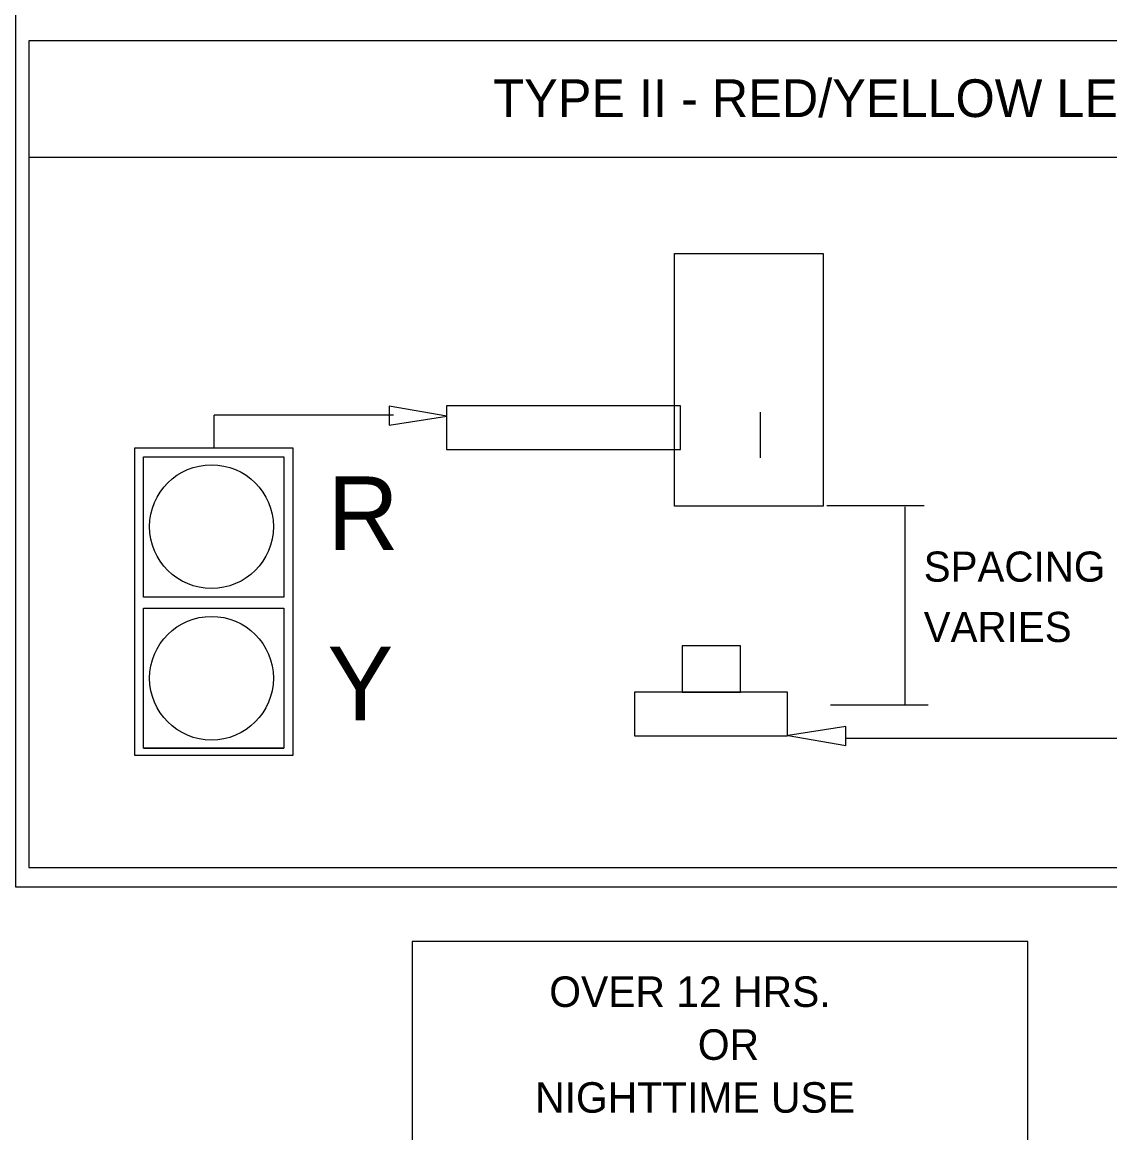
# Model space of a CAD drawing. Extents: x 21.7 to 29.1, y 5.9 to 16.2.
# Drawn here: x 25.794 to 27.525, y 11.205 to 12.972 of the extents above; entities that cross this region are included whole.
import ezdxf

# ---------------------------------------------------------------- set-up
doc = ezdxf.new("R2010")
doc.units = 0
for name, color, linetype in [('DETL-DIMS', 7, 'Continuous'), ('DETL-LINE', 7, 'Continuous'), ('DETL-NOTE', 7, 'Continuous')]:
    doc.layers.add(name, color=color, linetype=linetype)

msp = doc.modelspace()

# ---------------------------------------------------------------- linework, layer by layer
at = {"layer": 'DETL-DIMS'}
for p, q in [((27.0741, 12.2032), (27.2295, 12.2032)), ((27.1983, 12.2011), (27.1983, 11.886)), ((27.08, 11.886), (27.2354, 11.886))]:
    msp.add_line(p, q, dxfattribs=at)
for points in [[(26.3775, 12.3612), (26.3775, 12.3308), (26.4695, 12.3456)], [(27.1046, 11.8212), (27.1046, 11.8516), (27.0126, 11.8368)]]:
    msp.add_lwpolyline(points, close=True, dxfattribs=at)
at = {"layer": 'DETL-LINE'}
for p, q in [((26.3847, 12.3468), (26.0992, 12.3468)), ((26.0992, 12.2944), (26.0992, 12.3468)), ((26.9681, 12.3516), (26.9681, 12.2788)), ((25.9865, 12.0572), (25.9865, 12.2805)), ((25.9865, 12.2805), (26.2098, 12.2805)), ((26.2098, 12.2805), (26.2098, 12.0572)), ((26.2098, 12.0572), (25.9865, 12.0572)), ((25.9865, 11.8167), (25.9865, 12.0399)), ((25.9865, 12.0399), (26.2098, 12.0399)), ((26.2098, 12.0399), (26.2098, 11.8167)), ((27.1046, 11.833), (27.7835, 11.833)), ((25.9865, 11.8167), (26.2098, 11.8167)), ((26.2098, 11.8167), (25.9865, 11.8167)), ((27.3944, 11.5089), (26.4145, 11.5089)), ((26.4145, 11.5089), (26.4145, 7.6665)), ((27.3944, 7.6665), (27.3944, 11.5089))]:
    msp.add_line(p, q, dxfattribs=at)
for points in [[(25.7831, 11.5962), (29.0092, 11.5962), (29.0092, 14.3652), (25.7831, 14.3652)], [(25.8041, 11.6269), (28.9793, 11.6269), (28.9793, 12.9429), (25.8041, 12.9429)], [(28.9732, 12.7569), (25.8041, 12.7569), (25.8041, 11.6269), (28.9732, 11.6269)], [(26.8319, 12.2021), (26.8319, 12.6043), (27.0684, 12.6043), (27.0684, 12.2021)], [(26.8414, 12.3619), (26.469, 12.3619), (26.469, 12.2922), (26.8414, 12.2922)], [(25.9729, 12.295), (26.2243, 12.295), (26.2243, 11.805), (25.9729, 11.805)], [(26.844, 11.906), (26.937, 11.906), (26.937, 11.9796), (26.844, 11.9796)], [(26.7684, 11.906), (26.7684, 11.8365), (27.0119, 11.8365), (27.0119, 11.906)]]:
    msp.add_lwpolyline(points, close=True, dxfattribs=at)
for centre in [(26.0949, 12.1695), (26.0949, 11.9282)]:
    msp.add_circle(centre, 0.0985, dxfattribs=at)

# ---------------------------------------------------------------- texts
for s, p in [('OVER 12 HRS.', (26.6325, 11.405)), ('OR', (26.869, 11.3208)), ('NIGHTTIME USE', (26.61, 11.2366))]:
    msp.add_text(s, height=0.0486, dxfattribs=at).set_placement(p)
at = {"layer": 'DETL-NOTE'}
for s, height, p in [('TYPE II - RED/YELLOW LENS AFAD', 0.06, (26.5435, 12.8215)), ('R', 0.1172, (26.2796, 12.1322)), ('SPACING', 0.048, (27.2285, 12.0819)), ('VARIES', 0.048, (27.2285, 11.9859)), ('Y', 0.1172, (26.2796, 11.8611))]:
    msp.add_text(s, height=height, dxfattribs=at).set_placement(p)

doc.saveas('drawing.dxf')
